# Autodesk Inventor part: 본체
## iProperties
Created: 2014-11
Part Number: 본체
Document SubType Name: Modeling
Designer: tw009
Density: 2.71 g/cm^3
Material: 알루미늄-6061
Mass: 2801.42 g
Surface Area: 2059.46 cm^2
Volume: 1033.73 cm^3
Author: tw009
